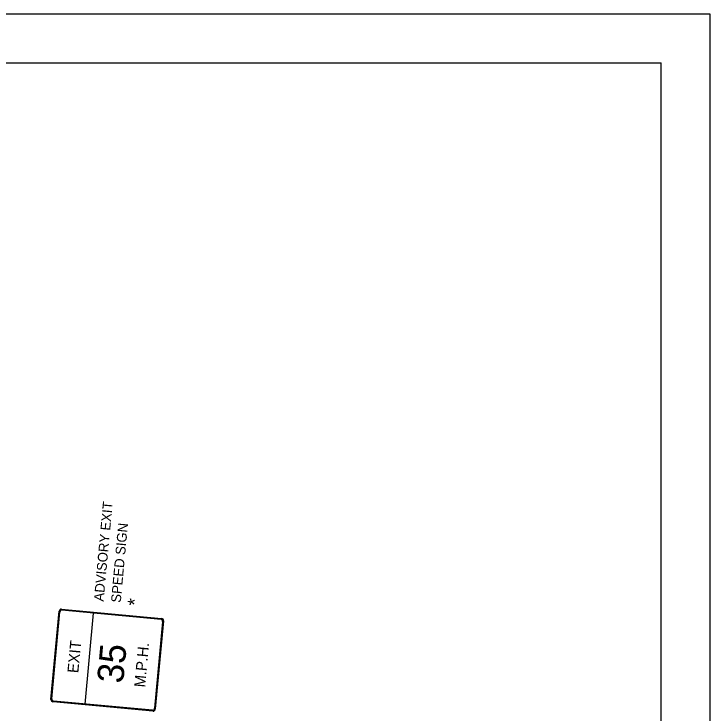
# Model space of a CAD drawing. Extents: x 644898 to 648326, y 298294 to 300670.
# Drawn here: x 648048.9 to 648262.3, y 300456 to 300670.5 of the extents above; entities that cross this region are included whole.
import ezdxf

# ---------------------------------------------------------------- set-up
doc = ezdxf.new("R2010")
doc.units = 0
for name, color, linetype in [('1', 7, 'Continuous'), ('2', 7, 'Continuous'), ('XCS-GRID-MIN', 7, 'Continuous')]:
    doc.layers.add(name, color=color, linetype=linetype)

msp = doc.modelspace()

# ---------------------------------------------------------------- linework, layer by layer
at = {"layer": '1'}
for p in [(647461.32, 300655.49), (648247.32, 300091.49)]:
    msp.add_line(p, (648247.32, 300655.49), dxfattribs=at)
at = {"layer": '2'}
for p, q in [((648063.45, 300487.87), (648094.07, 300484.99)), ((648060.2, 300460.12), (648062.7, 300487.24)), ((648060.45, 300460.37), (648062.95, 300486.99)), ((648063.57, 300487.62), (648093.95, 300484.74)), ((648070.7, 300458.74), (648073.2, 300486.62)), ((648094.45, 300483.99), (648091.95, 300457.49)), ((648094.7, 300484.24), (648092.2, 300457.24)), ((648091.45, 300456.49), (648060.82, 300459.37)), ((648091.32, 300456.87), (648060.95, 300459.62))]:
    msp.add_line(p, q, dxfattribs=at)
for centre, major_axis, start_param, end_param in [((648063.35, 300487.14), (-0.066, -0.711), 3.141593, 4.712389), ((648063.51, 300486.91), (-0.06, -0.652), 3.141593, 4.712389), ((648093.86, 300484.1), (0.06, 0.652), 4.712389, 6.283185), ((648094.07, 300484.29), (0.066, 0.711), 4.712389, 6.283185), ((648060.84, 300460.11), (-0.066, -0.711), 4.712389, 6.283185), ((648061.05, 300460.3), (-0.06, -0.652), 4.712389, 6.283185), ((648091.39, 300457.49), (0.06, 0.652), 3.141593, 4.712389), ((648091.56, 300457.26), (-0.066, -0.711), 0, 1.570796)]:
    msp.add_ellipse(centre, major_axis=major_axis, ratio=0.9, start_param=start_param, end_param=end_param, dxfattribs=at)
at = {"layer": 'XCS-GRID-MIN'}
msp.add_lwpolyline([(647421.32, 300670.49), (648262.32, 300670.49), (648262.32, 300076.49), (647421.32, 300076.49)], close=True, dxfattribs=at)

# ---------------------------------------------------------------- texts
at = {"layer": '2'}
for s, height, rotation, p in [('ADVISORY EXIT', 3, 84.7025, (648076.32, 300490.12)), ('SPEED SIGN', 3, 84.7025, (648081.57, 300489.74)), ('*', 4.32, 84.7025, (648087.89, 300488.68)), ('EXIT', 3.373, 84.7024, (648068.57, 300468.12)), ('M.P.H.', 3.373, 84.7031, (648089.07, 300463.74)), ('35', 8.062, 84.7025, (648082.32, 300464.87))]:
    msp.add_text(s, height=height, rotation=rotation, dxfattribs=at).set_placement(p)

doc.saveas('drawing.dxf')
